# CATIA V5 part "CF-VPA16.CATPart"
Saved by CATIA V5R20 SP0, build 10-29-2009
Part number: CF-VPA16
Bounding box of the stored display mesh (mm): x 0 to 39.5, y -8 to 8, z -8 to 8
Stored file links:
  C:\Users\Utente\Desktop\IO LAVORO\3D X SITO CF\X SITO\PLASTICA\CF-VPA\CF-VPA16.CATPart
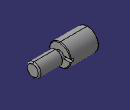
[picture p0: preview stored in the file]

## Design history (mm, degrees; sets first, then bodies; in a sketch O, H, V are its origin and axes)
Set1
  DatumSurface1 to DatumSurface30 "CF-VPA16"
Body1 (main body)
